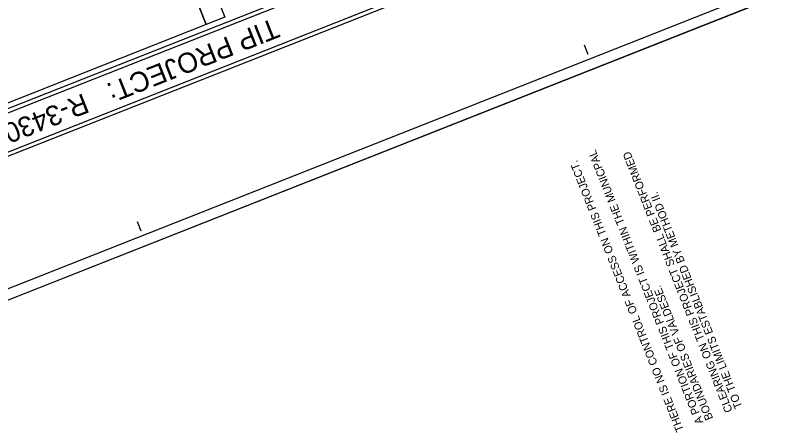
# Model space of a CAD drawing. Extents: x 1247235 to 1260080, y 742320 to 754020.
# Drawn here: x 1250319 to 1254624, y 742320 to 744667 of the extents above; entities that cross this region are included whole.
import ezdxf

# ---------------------------------------------------------------- set-up
doc = ezdxf.new("R2010")
doc.units = 0
for name, color, linetype in [('Scratch_Level_0', 7, 'Continuous'), ('Sheet Cutting Line CELL', 7, 'Continuous'), ('Sheet Data Field CELL', 7, 'Continuous'), ('Sheet Plot Border Inside CELL', 7, 'Continuous'), ('Sheet Plot Border Outside CELL', 7, 'Continuous'), ('Sheet Title CELL', 7, 'Continuous')]:
    doc.layers.add(name, color=color, linetype=linetype)

msp = doc.modelspace()

# ---------------------------------------------------------------- linework, layer by layer
at = {"layer": 'Scratch_Level_0'}
msp.add_lwpolyline([(1249947.5, 744043.6), (1249434.6, 745340.9), (1250878.3, 745911.7), (1251391.3, 744614.5)], close=True, dxfattribs=at)
at = {"layer": 'Sheet Cutting Line CELL'}
msp.add_line((1250021.3, 742966), (1254624.4, 744786.1), dxfattribs=at)
at = {"layer": 'Sheet Plot Border Inside CELL'}
msp.add_lwpolyline([(1254509, 744803.4), (1251751.5, 751777.2), (1247336.2, 750031.4), (1250093.7, 743057.5)], close=True, dxfattribs=at)
at = {"layer": 'Sheet Plot Border Outside CELL'}
msp.add_lwpolyline([(1247234.8, 750013.1), (1250021.3, 742966), (1254624.4, 744786.1), (1251837.9, 751833.2)], close=True, dxfattribs=at)
at = {"layer": 'Sheet Title CELL'}
for p, q in [((1254098, 745628), (1249829.6, 743940.2)), ((1253315.5, 745342.8), (1249821.3, 743961.2)), ((1253537.2, 744445.7), (1253516.5, 744498)), ((1253537.2, 744445.7), (1253516.5, 744498)), ((1251026.4, 743452.9), (1251005.7, 743505.2)), ((1251026.4, 743452.9), (1251005.7, 743505.2))]:
    msp.add_line(p, q, dxfattribs=at)
for points in [[(1251391.3, 744614.5), (1250878.3, 745911.7), (1250982.9, 745953.1), (1251495.9, 744655.8)], [(1249947.5, 744043.6), (1249434.6, 745340.9), (1250878.3, 745911.7), (1251391.3, 744614.5)]]:
    msp.add_lwpolyline(points, close=True, dxfattribs=at)
for points in [[(1249891.3, 743722.7), (1254201.7, 745427.1)], [(1249891.3, 743722.7), (1254201.6, 745427)], [(1249904, 743752), (1254172.4, 745439.7)]]:
    msp.add_lwpolyline(points, dxfattribs=at)

# ---------------------------------------------------------------- texts
at = {"layer": 'Sheet Data Field CELL'}
for s, p in [('A PORTION OF THIS PROJECT IS WITHIN THE MUNICPAL', (1254185.3, 742379)), ('CLEARING ON THIS PROJECT SHALL BE PERFORMED', (1254349.9, 742444.1)), ('THERE IS NO CONTROL OF ACCESS ON THIS PROJECT.', (1254075.6, 742335.6)), ('TO THE LIMITS ESTABLISHED BY METHOD II.', (1254404.7, 742465.8)), ('BOUNDARIES OF VALDESE.', (1254240.1, 742400.7))]:
    msp.add_text(s, height=45, rotation=111.5793, dxfattribs=at).set_placement(p)
at = {"layer": 'Sheet Title CELL'}
for s, p in [('TIP PROJECT:', (1251771.3, 744652.9)), ('R-3430B ', (1250701.8, 744230))]:
    msp.add_text(s, height=112.5, rotation=201.5743, dxfattribs=at).set_placement(p)

doc.saveas('drawing.dxf')
